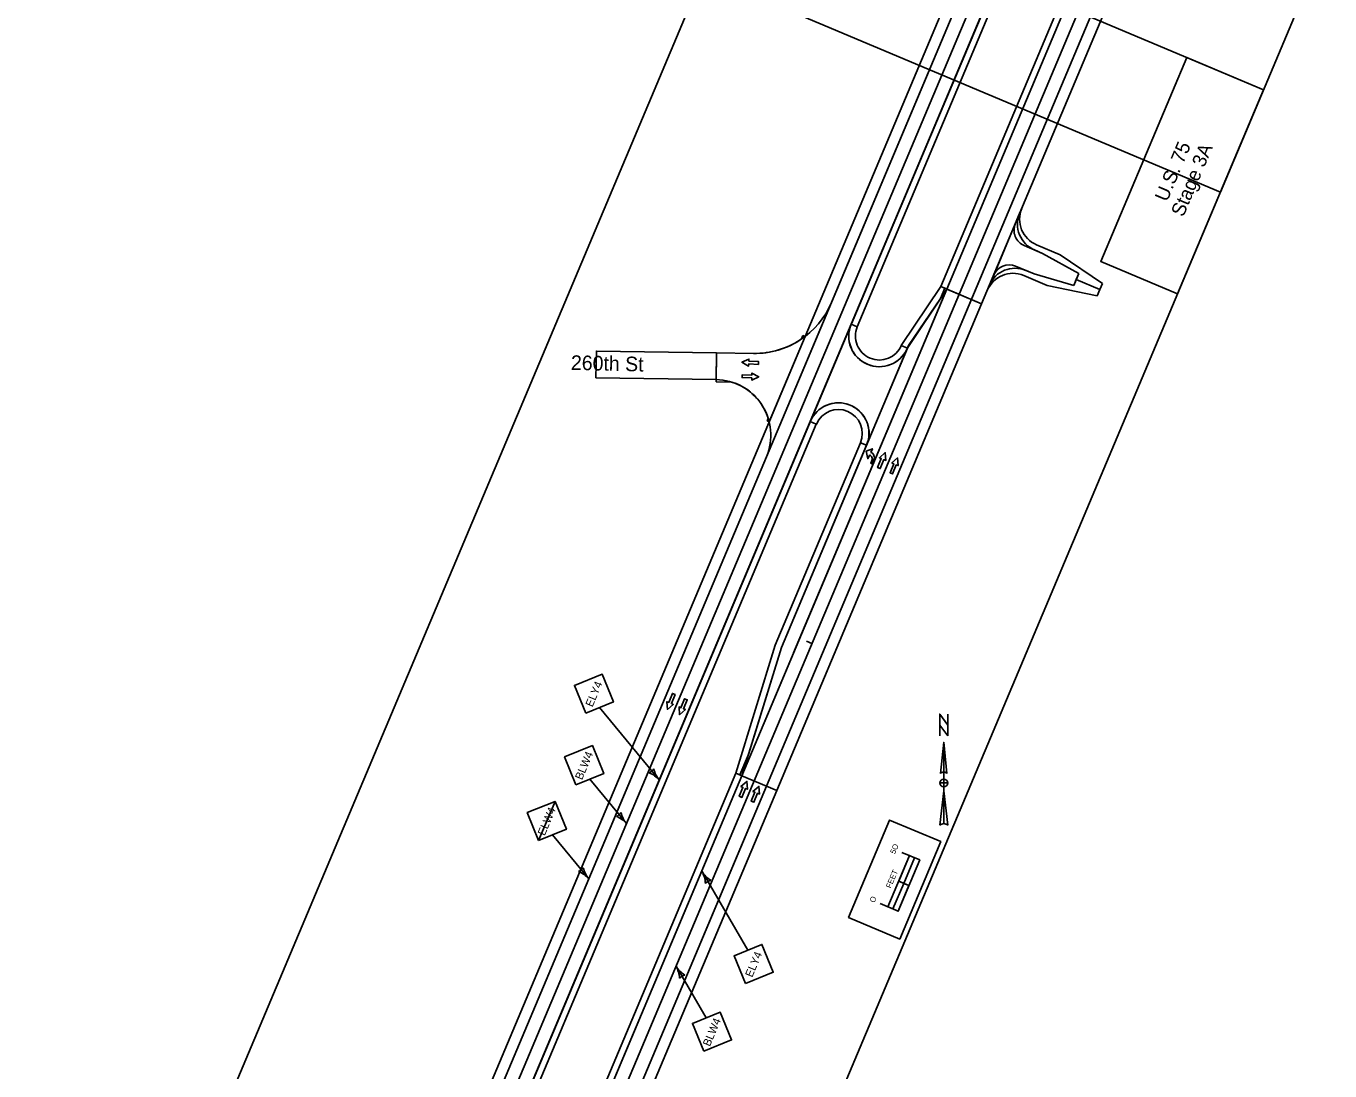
# Model space of a CAD drawing. Extents: x 14104283 to 14120882, y 8635219 to 8671666.
# Drawn here: x 14112889 to 14114062, y 8655356 to 8656296 of the extents above; entities that cross this region are included whole.
import ezdxf

# ---------------------------------------------------------------- set-up
doc = ezdxf.new("R2010")
doc.units = 0
for name, color, linetype in [('Cell', 7, 'Continuous'), ('dsnCellsNorthArrow', 7, 'Continuous'), ('dsnCellsScaleBlock', 7, 'Continuous'), ('dsnNonPlotable', 7, 'Continuous'), ('dsnPaintExistingEdgeLineRightWhite', 7, 'Continuous'), ('dsnPaintExistingLaneLineWhite', 7, 'Continuous'), ('dsnPaintPlaceBrokenLineWhite', 7, 'Continuous'), ('dsnPaintPlaceEdgeLineLeftYellow', 7, 'Continuous'), ('dsnPaintPlaceEdgeLineRightWhite', 7, 'Continuous'), ('dsnPaintRemoveDoubleCenterLineYellow', 7, 'Continuous'), ('dsnShadingGranular', 7, 'Continuous'), ('dsnShadingPaved', 7, 'Continuous'), ('dsnStdLabel', 7, 'Continuous'), ('dsnStgShadingPrevPav', 7, 'Continuous'), ('dsnTextFinalPlan', 7, 'Continuous'), ('dsnTextOverlapEven', 7, 'Continuous'), ('TextAlignmentLrg', 7, 'Continuous')]:
    doc.layers.add(name, color=color, linetype=linetype)

msp = doc.modelspace()

# ---------------------------------------------------------------- linework, layer by layer
at = {"layer": 'Cell'}
for p, q in [((14113648.5, 8655910.1), (14113648.2, 8655910.2)), ((14113649.3, 8655912.6), (14113649.4, 8655912.5))]:
    msp.add_line(p, q, dxfattribs=at)
for points in [[(14113548.3, 8655994.3), (14113548.2, 8655991.8), (14113539.5, 8655992.2), (14113539.4, 8655990.3), (14113533.3, 8655993.7), (14113539.7, 8655996.5), (14113539.6, 8655994.7)], [(14113533.5, 8655979.9), (14113533.6, 8655982.4), (14113542.3, 8655982.1), (14113542.4, 8655984), (14113548.5, 8655980.6), (14113542.2, 8655977.7), (14113542.2, 8655979.6)], [(14113657.8, 8655898), (14113655.5, 8655899), (14113658.8, 8655907.1), (14113657.1, 8655907.8), (14113662.4, 8655912.4), (14113662.9, 8655905.4), (14113661.1, 8655906.1)], [(14113669, 8655893.3), (14113666.7, 8655894.3), (14113670, 8655902.4), (14113668.3, 8655903.1), (14113673.5, 8655907.7), (14113674, 8655900.7), (14113672.3, 8655901.4)], [(14113470.9, 8655695.7), (14113473.2, 8655694.7), (14113469.9, 8655686.6), (14113471.6, 8655685.9), (14113466.3, 8655681.3), (14113465.8, 8655688.3), (14113467.5, 8655687.6)], [(14113481.8, 8655691), (14113484.2, 8655690), (14113480.8, 8655681.9), (14113482.6, 8655681.2), (14113477.3, 8655676.6), (14113476.8, 8655683.6), (14113478.5, 8655682.9)], [(14113533.3, 8655602.2), (14113530.9, 8655603.2), (14113534.3, 8655611.2), (14113532.5, 8655612), (14113537.8, 8655616.6), (14113538.3, 8655609.6), (14113536.6, 8655610.3)], [(14113544.1, 8655597.8), (14113541.7, 8655598.7), (14113545.1, 8655606.8), (14113543.3, 8655607.5), (14113548.6, 8655612.1), (14113549.1, 8655605.2), (14113547.4, 8655605.9)]]:
    msp.add_lwpolyline(points, close=True, dxfattribs=at)
for points in [[(14113539.6, 8655994.7), (14113539.7, 8655996.5), (14113533.3, 8655993.7), (14113539.4, 8655990.3), (14113539.5, 8655992.2), (14113548.2, 8655991.8), (14113548.3, 8655994.3), (14113539.6, 8655994.7)], [(14113542.2, 8655979.6), (14113542.2, 8655977.7), (14113548.5, 8655980.6), (14113542.4, 8655984), (14113542.3, 8655982.1), (14113533.6, 8655982.4), (14113533.5, 8655979.9), (14113542.2, 8655979.6)], [(14113645.1, 8655913.7), (14113650.8, 8655915.9), (14113649.3, 8655912.6)], [(14113645.1, 8655913.7), (14113650.8, 8655915.9), (14113649.3, 8655912.6)], [(14113648.2, 8655910.2), (14113646.6, 8655906.9), (14113645.1, 8655913.7)], [(14113648.2, 8655910.2), (14113646.6, 8655906.9), (14113645.1, 8655913.7)], [(14113648.5, 8655910.1), (14113648.2, 8655910.2)], [(14113649.3, 8655912.6), (14113649.4, 8655912.5)], [(14113652.1, 8655905.8), (14113650.7, 8655902.4), (14113649.3, 8655902.9), (14113650.3, 8655905.4)], [(14113652.1, 8655905.8), (14113650.7, 8655902.4), (14113649.3, 8655902.9), (14113650.3, 8655905.4)], [(14113661.1, 8655906.1), (14113662.9, 8655905.4), (14113662.4, 8655912.4), (14113657.1, 8655907.8), (14113658.8, 8655907.1), (14113655.5, 8655899), (14113657.8, 8655898), (14113661.1, 8655906.1)], [(14113672.3, 8655901.4), (14113674, 8655900.7), (14113673.5, 8655907.7), (14113668.3, 8655903.1), (14113670, 8655902.4), (14113666.7, 8655894.3), (14113669, 8655893.3), (14113672.3, 8655901.4)], [(14113467.5, 8655687.6), (14113465.8, 8655688.3), (14113466.3, 8655681.3), (14113471.6, 8655685.9), (14113469.9, 8655686.6), (14113473.2, 8655694.7), (14113470.9, 8655695.7), (14113467.5, 8655687.6)], [(14113478.5, 8655682.9), (14113476.8, 8655683.6), (14113477.3, 8655676.6), (14113482.6, 8655681.2), (14113480.8, 8655681.9), (14113484.2, 8655690), (14113481.8, 8655691), (14113478.5, 8655682.9)], [(14113536.6, 8655610.3), (14113538.3, 8655609.6), (14113537.8, 8655616.6), (14113532.5, 8655612), (14113534.3, 8655611.2), (14113530.9, 8655603.2), (14113533.3, 8655602.2), (14113536.6, 8655610.3)], [(14113547.4, 8655605.9), (14113549.1, 8655605.2), (14113548.6, 8655612.1), (14113543.3, 8655607.5), (14113545.1, 8655606.8), (14113541.7, 8655598.7), (14113544.1, 8655597.8), (14113547.4, 8655605.9)]]:
    msp.add_lwpolyline(points, dxfattribs=at)
for centre, major_axis in [((14113647.1, 8655906.7), (-1.38, -3.41)), ((14113647.1, 8655906.7), (-1.38, -3.41)), ((14113647.5, 8655907.7), (-1.97, -4.87)), ((14113647.5, 8655907.7), (-1.97, -4.87))]:
    msp.add_ellipse(centre, major_axis=major_axis, ratio=0.9474, start_param=1.570796, end_param=3.141593, dxfattribs=at)
at = {"layer": 'dsnCellsNorthArrow'}
for p, q in [((14113715, 8655651.8), (14113717.8, 8655623.7)), ((14113715, 8655651.8), (14113715, 8655578.6)), ((14113712.1, 8655623.7), (14113712.1, 8655623.7)), ((14113712.3, 8655623.9), (14113712.8, 8655624.5)), ((14113715, 8655611.7), (14113715, 8655611.7)), ((14113711.4, 8655577.2), (14113715, 8655608.2))]:
    msp.add_line(p, q, dxfattribs=at)
msp.add_lwpolyline([(14113718.5, 8655657.5), (14113711.4, 8655667.3), (14113711.4, 8655677.2), (14113718.5, 8655667.3)], close=True, dxfattribs=at)
for points in [[(14113711.4, 8655657.5), (14113711.4, 8655677.2), (14113718.5, 8655667.3), (14113718.5, 8655677.2)], [(14113712.1, 8655623.7), (14113715, 8655651.8), (14113715, 8655625.1)], [(14113715, 8655611.7), (14113715, 8655615.2), (14113711.4, 8655615.2)], [(14113718.5, 8655615.2), (14113715, 8655615.2), (14113715, 8655618.7)], [(14113715, 8655578.6), (14113715, 8655608.2), (14113718.5, 8655577.2)]]:
    msp.add_lwpolyline(points, dxfattribs=at)
for centre, radius, start, end in [((14113715, 8655621.5), 3.52, 90.0204, 143.1257), ((14113715, 8655621.5), 3.52, 36.8481, 90.0218), ((14113715, 8655615.2), 3.52, 90, 180), ((14113715, 8655615.2), 3.52, 180, 270), ((14113715, 8655615.2), 3.52, 0, 90), ((14113715, 8655615.2), 3.52, 270, 360), ((14113715, 8655573.5), 5.1, 89.9894, 133.619), ((14113715, 8655573.5), 5.11, 46.4021, 90.0006)]:
    msp.add_arc(centre, radius, start, end, dxfattribs=at)
at = {"layer": 'dsnCellsScaleBlock'}
msp.add_line((14113683.7, 8655522.9), (14113674.5, 8655526.8), dxfattribs=at)
msp.add_line((14113683.7, 8655522.9), (14113674.5, 8655526.8), dxfattribs=at)
for points in [[(14113675.4, 8655474.8), (14113629.3, 8655494.2), (14113666.2, 8655581.8), (14113712.3, 8655562.4)], [(14113629.3, 8655494.2), (14113666.2, 8655581.8), (14113712.3, 8655562.4), (14113675.4, 8655474.8)], [(14113675.4, 8655474.8), (14113629.3, 8655494.2), (14113666.2, 8655581.8), (14113712.3, 8655562.4)], [(14113679, 8655524.8), (14113688.7, 8655547.9), (14113684.2, 8655549.8), (14113674.5, 8655526.8)], [(14113674, 8655499.8), (14113683.7, 8655522.9), (14113679, 8655524.8), (14113669.3, 8655501.8)]]:
    msp.add_lwpolyline(points, close=True, dxfattribs=at)
for points in [[(14113657.8, 8655506.6), (14113674, 8655499.8), (14113693.4, 8655545.9), (14113677.3, 8655552.7)], [(14113664.8, 8655503.7), (14113684.2, 8655549.8)]]:
    msp.add_lwpolyline(points, dxfattribs=at)
at = {"layer": 'dsnNonPlotable'}
for points in [[(14113498.5, 8656342.8), (14114107.1, 8657787.4), (14114572.5, 8657591.3), (14113963.9, 8656146.8)], [(14112928.7, 8654990.5), (14113537.3, 8656435), (14114002.7, 8656238.9), (14113394.1, 8654794.4)]]:
    msp.add_lwpolyline(points, close=True, dxfattribs=at)
at = {"layer": 'dsnPaintExistingEdgeLineRightWhite'}
msp.add_line((14110924.4, 8649364.5), (14118862.5, 8668214.7), dxfattribs=at)
at = {"layer": 'dsnPaintExistingLaneLineWhite'}
msp.add_line((14113579.9, 8655732.3), (14113656.6, 8655914.3), dxfattribs=at)
at = {"layer": 'dsnPaintPlaceBrokenLineWhite'}
for p, q in [((14110829.5, 8649404.5), (14118424.3, 8667439.6)), ((14110913.3, 8649369.2), (14114932.5, 8658913.4))]:
    msp.add_line(p, q, dxfattribs=at)
at = {"layer": 'dsnPaintPlaceEdgeLineLeftYellow'}
for p, q in [((14115779.3, 8661127.7), (14113631.7, 8656027.9)), ((14113717.7, 8656059.5), (14115716.8, 8660806.7)), ((14113682.1, 8656006), (14113717.7, 8656059.5)), ((14113594.8, 8655940.3), (14111420.5, 8650777)), ((14113568.9, 8655737), (14113646.5, 8655921.3)), ((14113533.3, 8655621.7), (14113568.9, 8655737)), ((14111505.3, 8650805.9), (14113533.3, 8655621.7))]:
    msp.add_line(p, q, dxfattribs=at)
for centre, radius, start, end in [((14113657, 8656017.2), 27.5, 157.1633, 335.9016), ((14113620.2, 8655929.6), 27.6, 342.4922, 157.0396)]:
    msp.add_arc(centre, radius, start, end, dxfattribs=at)
at = {"layer": 'dsnPaintPlaceEdgeLineRightWhite'}
for p, q in [((14115734.9, 8661084), (14113613.9, 8656047.5)), ((14113555.5, 8655908.7), (14111402.9, 8650797.1))]:
    msp.add_line(p, q, dxfattribs=at)
at = {"layer": 'dsnPaintRemoveDoubleCenterLineYellow'}
msp.add_line((14110913.3, 8649369.2), (14114932.5, 8658913.4), dxfattribs=at)
at = {"layer": 'dsnShadingGranular'}
for p, q in [((14113783.2, 8656127.5), (14113779.3, 8656118.3)), ((14113779.3, 8656118.3), (14113759.9, 8656072.2)), ((14113759.9, 8656072.2), (14113756.1, 8656063))]:
    msp.add_line(p, q, dxfattribs=at)
at = {"layer": 'dsnShadingPaved'}
for p, q in [((14113717.7, 8656059.5), (14115716.8, 8660806.7)), ((14115738.9, 8660797.4), (14113555.5, 8655612.4)), ((14113533.3, 8655621.7), (14113717.7, 8656059.5)), ((14113717.5, 8656059), (14113533.3, 8655621.7)), ((14113682.1, 8656006), (14113717.2, 8656058.5)), ((14113555.5, 8655908.7), (14113613.9, 8656047.5)), ((14113594.8, 8655940.3), (14113631.7, 8656027.9)), ((14113510.5, 8656002.1), (14113510.1, 8655978.1)), ((14113543.7, 8656001.6), (14113510.5, 8656002.1)), ((14113568.9, 8655737), (14113645.5, 8655919)), ((14113533.3, 8655621.7), (14113568.9, 8655737)), ((14111505.5, 8650806.3), (14113533.3, 8655621.7)), ((14113533.3, 8655621.7), (14113555.5, 8655612.4)), ((14113555.5, 8655612.4), (14113533.3, 8655621.7)), ((14113555.5, 8655612.4), (14110924.4, 8649364.5))]:
    msp.add_line(p, q, dxfattribs=at)
for points in [[(14118413.2, 8667444.3), (14110818.4, 8649409.2), (14109142.6, 8645431.4)], [(14109164.7, 8645422.1), (14110840.5, 8649399.8), (14118435.4, 8667434.9)]]:
    msp.add_lwpolyline(points, dxfattribs=at)
for centre, radius, start, end in [((14113544.8, 8656076.6), 75, 269.1633, 337.1633), ((14113657, 8656017.2), 27.5, 157.1633, 247.1633), ((14113657, 8656017.2), 27.5, 247.1633, 335.9016), ((14113509.4, 8655928.1), 50, 337.1633, 89.1633), ((14113620.2, 8655929.7), 27.5, 67.1633, 157.1633), ((14113620.2, 8655929.7), 27.5, 337.1633, 67.1633)]:
    msp.add_arc(centre, radius, start, end, dxfattribs=at)
at = {"layer": 'dsnStdLabel'}
for p, q in [((14113405.3, 8655683), (14113459, 8655617.9)), ((14113396.5, 8655618.7), (14113429.5, 8655578.7)), ((14113350.4, 8655563.4), (14113365.2, 8655598.6)), ((14113362.9, 8655568.5), (14113395.5, 8655529)), ((14113497.5, 8655535.5), (14113538.8, 8655464.8)), ((14113474.2, 8655450.3), (14113501.3, 8655403.9))]:
    msp.add_line(p, q, dxfattribs=at)
for points in [[(14113392.8, 8655677.9), (14113417.8, 8655688.1), (14113407.6, 8655713.1), (14113382.6, 8655702.9)], [(14113384, 8655613.6), (14113409, 8655623.7), (14113398.8, 8655648.8), (14113373.8, 8655638.6)], [(14113350.4, 8655563.4), (14113375.4, 8655573.6), (14113365.2, 8655598.6), (14113340.2, 8655588.5)], [(14113536.5, 8655434.7), (14113561.5, 8655444.9), (14113551.3, 8655469.9), (14113526.3, 8655459.7)], [(14113499, 8655373.8), (14113524, 8655384), (14113513.8, 8655409), (14113488.8, 8655398.8)]]:
    msp.add_lwpolyline(points, close=True, dxfattribs=at)
for centre, radius, start, end in [((14113446.5, 8655632.5), 8.86, 292.8385, 328.307), ((14113441.6, 8655603), 22.9, 40.5727, 68.6439), ((14113476.5, 8655632.8), 22.9, 192.5015, 220.5728), ((14113417, 8655593.3), 8.86, 292.8385, 328.307), ((14113446.9, 8655593.6), 22.9, 192.5015, 220.5728), ((14113412.1, 8655563.8), 22.9, 40.5727, 68.6439), ((14113383, 8655543.6), 8.86, 292.8385, 328.307), ((14113378.1, 8655514.1), 22.9, 40.5727, 68.6439), ((14113413, 8655543.9), 22.9, 192.5015, 220.5728), ((14113477.6, 8655524), 22.9, 2.1566, 30.2279), ((14113517.3, 8655547.1), 22.9, 210.2277, 238.299), ((14113507.2, 8655518.9), 8.86, 102.4935, 137.962), ((14113454.3, 8655438.7), 22.9, 2.1566, 30.2279), ((14113494, 8655461.8), 22.9, 210.2277, 238.299), ((14113483.9, 8655433.7), 8.86, 102.4935, 137.962)]:
    msp.add_arc(centre, radius, start, end, dxfattribs=at)
at = {"layer": 'dsnStgShadingPrevPav'}
for p, q in [((14110809.2, 8649413), (14118404, 8667448.1)), ((14118413.2, 8667444.3), (14110818.4, 8649409.2)), ((14115779.3, 8661127.7), (14113631.7, 8656027.9)), ((14113613.9, 8656047.5), (14115734.9, 8661084)), ((14115711.3, 8660809.1), (14113712.2, 8656061.8)), ((14113749, 8656046.3), (14115748.2, 8660793.5)), ((14113783.2, 8656127.5), (14113779.3, 8656118.3)), ((14113785.2, 8656132.1), (14113783.2, 8656127.5)), ((14113779.3, 8656118.3), (14113759.9, 8656072.2)), ((14113803.9, 8656091.6), (14113787.3, 8656098.6)), ((14113787.3, 8656098.6), (14113796.6, 8656094.7)), ((14113796.6, 8656094.7), (14113803.9, 8656091.6)), ((14113819.7, 8656090.4), (14113798.5, 8656099.4)), ((14113836.4, 8656073.6), (14113803.9, 8656091.6)), ((14113803.9, 8656091.6), (14113836.4, 8656073.6)), ((14113779.6, 8656080.2), (14113796.2, 8656073.2)), ((14113788.8, 8656076.3), (14113779.6, 8656080.2)), ((14113857.7, 8656064.7), (14113819.7, 8656090.4)), ((14113759.9, 8656072.2), (14113756.1, 8656063)), ((14113786.9, 8656071.7), (14113808.1, 8656062.8)), ((14113796.2, 8656073.2), (14113788.8, 8656076.3)), ((14113796.2, 8656073.2), (14113831.9, 8656062.8)), ((14113831.9, 8656062.8), (14113796.2, 8656073.2)), ((14113831.9, 8656062.8), (14113836.4, 8656073.6)), ((14113834.1, 8656068.1), (14113831.9, 8656062.8)), ((14113836.4, 8656073.6), (14113834.1, 8656068.1)), ((14113855.3, 8656059.1), (14113834.1, 8656068.1)), ((14113834.1, 8656068.1), (14113855.3, 8656059.1)), ((14113712.2, 8656061.8), (14113749, 8656046.3)), ((14113756.1, 8656063), (14113754.1, 8656058.4)), ((14113808.1, 8656062.8), (14113852.9, 8656053.4)), ((14113852.9, 8656053.4), (14113855.3, 8656059.1)), ((14113855.3, 8656059.1), (14113857.7, 8656064.7)), ((14113555.5, 8655908.7), (14113613.9, 8656047.5)), ((14113594.8, 8655940.3), (14113631.7, 8656027.9)), ((14113631.7, 8656027.9), (14113594.8, 8655940.3)), ((14113631.7, 8656027.9), (14113637.2, 8656025.6)), ((14113590.2, 8656016.9), (14113557.9, 8655940.2)), ((14113587.1, 8656014.7), (14113588.3, 8656017.7)), ((14113588.3, 8656017.7), (14113590.2, 8656016.9)), ((14113676.8, 8656008.9), (14113682.4, 8656006.5)), ((14113510.1, 8655976.1), (14113510.5, 8656002.1)), ((14113510.5, 8656002.1), (14113543.7, 8656001.6)), ((14113682.4, 8656006.5), (14113645.5, 8655919)), ((14113524.1, 8655975.9), (14113510.1, 8655976.1)), ((14113594.8, 8655940.3), (14111420.5, 8650777)), ((14113556, 8655941), (14113557, 8655943.3)), ((14113557.9, 8655940.2), (14113556, 8655941)), ((14113600.3, 8655938), (14113594.8, 8655940.3)), ((14113645.5, 8655919), (14113640, 8655921.3)), ((14111402.9, 8650797.1), (14113555.5, 8655908.7)), ((14113533.3, 8655621.7), (14111505.5, 8650806.3)), ((14113564.7, 8655608.5), (14113533.3, 8655621.7)), ((14111352.5, 8650355.3), (14113564.7, 8655608.5))]:
    msp.add_line(p, q, dxfattribs=at)
for points in [[(14115784.8, 8661125.3), (14113637.2, 8656025.6), (14113631.7, 8656027.9), (14115779.3, 8661127.7)], [(14113533.3, 8655621.7), (14113531.5, 8655622.5), (14113539.3, 8655640.9), (14113568.9, 8655737), (14113683.3, 8656008.9), (14113712, 8656051.1), (14113715.8, 8656060.3), (14113717.7, 8656059.5)], [(14113533.3, 8655621.7), (14113717.7, 8656059.5), (14113749, 8656046.3), (14113564.7, 8655608.5)], [(14113676.8, 8656008.9), (14113712.2, 8656061.8), (14113715.8, 8656060.3), (14113712, 8656051.1), (14113683.3, 8656008.9), (14113682.4, 8656006.5)], [(14113402, 8655979.7), (14113402.4, 8656003.7), (14113510.5, 8656002.1), (14113510.1, 8655978.1)], [(14113600.3, 8655938), (14111426, 8650774.7), (14111420.5, 8650777), (14113594.8, 8655940.3)], [(14113527.8, 8655624.1), (14113563.3, 8655739.3), (14113640, 8655921.3), (14113645.5, 8655919), (14113568.9, 8655737), (14113539.3, 8655640.9), (14113531.5, 8655622.5)], [(14111465.6, 8650758), (14111500, 8650808.6), (14113527.8, 8655624.1), (14113533.3, 8655621.7), (14111505.5, 8650806.3), (14111503.6, 8650807.1), (14111499.8, 8650797.8), (14111471.1, 8650755.6)]]:
    msp.add_lwpolyline(points, close=True, dxfattribs=at)
for centre, radius, start, end in [((14113806.3, 8656117.8), 25, 157.1633, 247.1633), ((14113806.3, 8656117.8), 25, 157.1633, 247.1633), ((14113808.2, 8656122.4), 25, 157.1651, 247.1633), ((14113793.2, 8656112.5), 15, 157.1633, 247.1633), ((14113793.2, 8656112.5), 15, 157.1633, 247.1633), ((14113773.8, 8656066.4), 15, 67.1633, 157.1633), ((14113773.8, 8656066.4), 15, 67.1633, 157.1633), ((14113777.2, 8656048.7), 25, 67.1633, 157.1619), ((14113779.1, 8656053.3), 25, 67.1633, 157.1633), ((14113779.1, 8656053.3), 25, 67.1633, 157.1633), ((14113657, 8656017.2), 21.5, 157.1633, 247.1633), ((14113544.8, 8656076.6), 75, 269.1633, 304.3034), ((14113657, 8656017.2), 21.5, 247.1633, 337.1633), ((14113509.4, 8655928.1), 50, 17.6991, 72.9031), ((14113620.2, 8655929.7), 21.5, 67.1633, 157.1633), ((14113620.2, 8655929.7), 21.5, 337.1633, 67.1633)]:
    msp.add_arc(centre, radius, start, end, dxfattribs=at)
at = {"layer": 'dsnTextOverlapEven'}
for points in [[(14114002.7, 8656238.9), (14113925.3, 8656055.3), (14113856.2, 8656084.4), (14113933.6, 8656268)], [(14113856.2, 8656084.4), (14113933.6, 8656268), (14114002.7, 8656238.9), (14113925.3, 8656055.3)]]:
    msp.add_lwpolyline(points, close=True, dxfattribs=at)
at = {"layer": 'TextAlignmentLrg'}
msp.add_line((14113596.4, 8655740.7), (14113591.4, 8655742.8), dxfattribs=at)
msp.add_line((14113596.4, 8655740.7), (14113591.4, 8655742.8), dxfattribs=at)

# ---------------------------------------------------------------- texts
at = {"layer": 'dsnCellsScaleBlock'}
for s, p in [('5O', (14113671.1, 8655550.9)), ('FEET', (14113667.3, 8655520)), ('O', (14113652.6, 8655507.1))]:
    msp.add_text(s, height=5, rotation=67.1547, dxfattribs=at).set_placement(p)
at = {"layer": 'dsnStdLabel'}
for s, p in [('ELY4', (14113398.9, 8655683)), ('BLW4', (14113389.5, 8655617.4)), ('ELW4', (14113355.9, 8655567.2)), ('ELY4', (14113542.6, 8655439.8)), ('BLW4', (14113504.5, 8655377.6))]:
    msp.add_text(s, height=7.2, rotation=67.1547, dxfattribs=at).set_placement(p)
at = {"layer": 'dsnTextFinalPlan'}
msp.add_text('260th St', height=13.12, rotation=358.6374, dxfattribs=at).set_placement((14113379.4, 8655986.9))
at = {"layer": 'dsnTextOverlapEven'}
for s, p in [('U.S. 75', (14113915.9, 8656137.4)), ('Stage 3A', (14113930.5, 8656123.8))]:
    msp.add_text(s, height=12.5, rotation=67.1547, dxfattribs=at).set_placement(p)

doc.saveas('drawing.dxf')
